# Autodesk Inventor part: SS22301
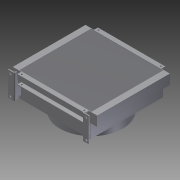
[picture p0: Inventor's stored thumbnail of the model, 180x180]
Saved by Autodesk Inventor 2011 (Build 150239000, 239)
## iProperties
Created: 2011-08
Part Number: SS22301
Document SubType Name: Modeling
Designer: khramov
Density: 1 g/cm^3
Author: khramov
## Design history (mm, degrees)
sketch "Эскиз1"
  geometry: L1 (0, 0)-(54, 0); L2 (538, 0)-(538, -464); L3 (538, -464)-(484, -464); L4 (0, -464)-(0, 0); L5 (0, -232)-(538, -232); L6 (54, 0)-(54, 25); L7 (54, 25)-(484, 25); L8 (484, 25)-(484, 0); L9 (484, 0)-(538, 0); L10 (54, -464)-(54, -489); L11 (54, -489)-(484, -489); L12 (484, -489)-(484, -464); L13 (54, -464)-(0, -464); L14 (70, 12.5)-(468, 12.5); L15 (468, 12.5)-(468, -476.5); L16 (468, -476.5)-(70, -476.5); L17 (70, -476.5)-(70, 12.5); L18 (269, 25)-(269, -489); C1 r 4.5 at (70, 12.5); C2 r 4.5 at (468, 12.5); C3 r 4.5 at (468, -476.5); C4 r 4.5 at (70, -476.5)
  constraints: 36 end point, 7 parallel, 7 perpendicular, 4 centre point, 4 coincident, 4 midpoint, 4 symmetric about line, 3 horizontal, 1 point on line
  dimensions: "d4" = 9 diameter of C4; "d5" = 9 diameter of C3; "d7" = 9 diameter of C1; "d38" = 538 distance between parallel lines of L2 L4; "d39" = 430 distance of L6.end L7.end; "d40" = 54 distance between parallel lines of L6 L4; "d41" = 25 distance of L1.end L6.end; "d42" = 514 distance between parallel lines of L11 L7; "d43" = 489 distance of L16.end L14.start; "d44" = 244.5 distance between parallel lines of L14 L5; "d45" = 398 distance of L14.start L14.end; "d46" = 199 distance between parallel lines of L18 L15; "d47" = 9 diameter of C2
extrude "Выдавливание1" new body sketch "Эскиз1" distance "d13" = 63; taper "d14" = 0 deg
sketch "Эскиз2"
  geometry: L1 (0, 0)-(54, 0) reference; L2 (54, -489)-(54, -464) reference; L3 (484, -464)-(484, -489) reference; L4 (538, -464)-(484, -464) reference; L5 (39, -3)-(499, -3); L6 (499, -3)-(499, -461); L7 (499, -461)-(39, -461); L8 (39, -461)-(39, -3)
  constraints: 8 end point, 2 parallel, 1 horizontal, 1 perpendicular
  dimensions: "d15" = 3 distance between parallel lines of L5 L1; "d16" = 3 distance between parallel lines of L7 L4; "d17" = 15 distance between parallel lines of L6 L3; "d18" = 15 distance between parallel lines of L2 L8
extrude "Выдавливание2" cut sketch "Эскиз2" distance "d19" = 2; taper "d20" = 0 deg
sketch "Эскиз3"
  geometry: L1 (-63, 25)-(-63, 0) reference; L2 (0, 25)-(0, 0) reference; L3 (0, 25)-(-63, 25) reference; L4 (-57, 25)-(-6, 25); L5 (-6, 25)-(-6, 0); L6 (-6, 0)-(-57, 0); L7 (-57, 0)-(-57, 25); L8 (0, -489)-(-63, -489) reference; L9 (-57, -489)-(-6, -489); L10 (-6, -489)-(-6, -464); L11 (-6, -464)-(-57, -464); L12 (-57, -464)-(-57, -489); L13 (0, 0)-(0, -464) reference; L14 (-63, 0)-(-63, -464) reference
  constraints: 16 end point, 4 parallel, 2 horizontal, 2 perpendicular, 2 point on line
  dimensions: "d21" = 6 distance between parallel lines of L7 L1; "d22" = 6 distance between parallel lines of L2 L5; "d23" = 25 distance between parallel lines of L6 L3; "d24" = 25 distance of L9.end L10.end; "d25" = 6 distance between parallel lines of L13 L10; "d26" = 6 distance between parallel lines of L14 L12
extrude "Выдавливание3" cut sketch "Эскиз3" stored distance "d27" = 2; taper "d28" = 0 deg
sketch "Эскиз4"
  geometry: L1 (0, 0)-(-54, 0) reference; L2 (-54, 0)-(-54, 25) reference; L3 (-484, 25)-(-484, 0) reference; L4 (-494, 0)-(-44, 0); L5 (-44, 0)-(-44, -464); L6 (-44, -464)-(-494, -464); L7 (-494, -464)-(-494, 0)
  constraints: 8 end point, 2 parallel, 1 horizontal, 1 perpendicular, 1 point on line
  dimensions: "d48" = 464 distance of L4.end L5.end; "d49" = 10 distance between parallel lines of L3 L7; "d50" = 10 distance between parallel lines of L2 L5
extrude "Выдавливание4" join sketch "Эскиз4" distance "d51" = 90; taper "d52" = 0 deg
sketch "Эскиз5"
  geometry: L1 (-494, 0)-(-44, -464); L2 (-44, 0)-(-494, -464); C1 r 200 at (-269, -232); 1 further point
  constraints: 4 end point, 1 centre point, 1 midpoint
  dimensions: "d53" = 400 diameter of C1
extrude "Выдавливание5" join sketch "Эскиз5" distance "d54" = 70; taper "d55" = 0 deg
sketch "Эскиз6"
  geometry: L1 (-269, -232)-(-269, -734.409); L2 (-484, -489)-(-54, -489) reference; L3 (-538, -464)-(-494, -464) reference; L4 (-491.5, -464)-(-491.5, -494); L5 (-497.5, -500)-(-526.5, -500); L6 (-526.5, -500)-(-526.5, -506); L7 (-526.5, -506)-(-491.5, -506); L8 (-485.5, -500)-(-485.5, -464); L9 (-511.5, -503.753)-(-511.5, -569.856); L10 (-11.5, -500)-(-11.5, -506); L11 (-11.5, -506)-(-46.5, -506); L12 (-40.5, -500)-(-11.5, -500); L13 (-46.5, -464)-(-46.5, -494); L14 (-52.5, -500)-(-52.5, -464); L15 (-26.5, -503.753)-(-26.5, -569.856); L16 (-491.5, -464)-(-485.5, -464); L17 (-538, -464)-(-484, -464) reference; L18 (-52.5, -464)-(-46.5, -464); L19 (-54, -464)-(0, -464) reference; C1 r 200 at (-269, -232) reference; A1 r 6 centre (-497.5, -494) between (-497.5, -500) and (-491.5, -494); A2 r 6 centre (-491.5, -500) between (-491.5, -506) and (-485.5, -500); A3 r 6 centre (-40.5, -494) between (-46.5, -494) and (-40.5, -500); A4 r 6 centre (-46.5, -500) between (-52.5, -500) and (-46.5, -506); 2 further points
  constraints: 31 end point, 13 symmetric about line, 8 point on circle, 4 centre point, 4 tangent, 3 parallel, 2 collinear, 2 perpendicular, 1 equal radius, 1 point on line, 2 other
  dimensions: "d56" = 6 distance of L5.end L6.end; "d57" = 6 distance between parallel lines of L4 L8; "d59" = 15 distance between parallel lines of L9 L6; "d60" = 20 distance between parallel lines of L4 L9; "d62" = 6 radius of A1; "d75" = 485 distance between parallel lines of L9 L15
extrude "Выдавливание6" join sketch "Эскиз6" distance "d63" = 166; taper "d65" = 0 deg; dims "d64" = 1, "d66" = 0
sketch "Эскиз7"
  geometry: L1 (-500, 15)-(-15, 15); L2 (-15, 15)-(-15, 141); L3 (-15, 141)-(-500, 141); L4 (-500, 141)-(-500, 15); L5 (-457.5, 236)-(-57.5, 236) reference; L6 (-257.5, 236)-(-257.5, 402.493); L7 (-472.5, 13)-(-42.5, 13) reference; C1 r 6.5 at (-500, 141); C2 r 6.5 at (-500, 15); C3 r 6.5 at (-15, 141); C4 r 6.5 at (-15, 15); 1 further point
  constraints: 10 end point, 4 centre point, 4 coincident, 2 parallel, 2 perpendicular, 1 horizontal, 1 midpoint
  dimensions: "d67" = 13 diameter of C1; "d68" = 13 diameter of C2; "d69" = 13 diameter of C3; "d70" = 13 diameter of C4; "d71" = 485 distance of L2.end L3.end; "d72" = 126 distance of L3.end L1.start; "d73" = 242.5 distance between parallel lines of L6 L4; "d76" = 2 distance between parallel lines of L1 L7
extrude "Выдавливание7" cut sketch "Эскиз7" distance "d77" = 10; taper "d78" = 0 deg
sketch "Эскиз8"
  geometry: L1 (-166, 15.676)-(-77.058, 26.142); L2 (-77.058, 26.142)-(-77.058, 42); L3 (-166, 42)-(-166, 15.676); L4 (-166, 42)-(-77.058, 42); L5 (-23.748, 26.142)-(-23.748, 42); L6 (-23.748, 42)-(-12.683, 42); L7 (-23.748, 26.142)-(-10, 16.534); L8 (-10, 0)-(0, 0); L9 (0, 0)-(0, 42); L10 (0, 42)-(-23.748, 42); L11 (-10, 16.534)-(-10, 0); 1 further point
  constraints: 22 end point, 3 perpendicular, 1 vertical
  dimensions: "d79" = 10 distance between parallel lines of L9 L11
extrude "Выдавливание8" cut sketch "Эскиз8" stored distance "d80" = 10; taper "d81" = 0 deg
sketch "Эскиз9"
  geometry: L1 (-166, 6)-(-166, 36) reference; L2 (-166, 8.721)-(-166, 36); L3 (-166, 36)-(-77.058, 36); L4 (-77.058, 20.142)-(-77.058, 36) reference; L5 (-77.058, 36)-(-77.058, 20.142); L6 (-77.058, 20.142)-(-166, 9.676); L7 (-77.058, 20.142)-(-166, 9.676) reference; L8 (0, 36)-(0, -6); L9 (0, 36)-(0, 0) reference; L10 (0, -6)-(-10, -6); L11 (-10, -6)-(-10, 0) reference; L12 (-10, -6)-(-10, 10.534); L13 (-10, 10.534)-(-23.748, 20.142); L14 (-10, 10.534)-(-23.748, 20.142) reference; L15 (-23.748, 20.142)-(-23.748, 36); L16 (-153, 36)-(0, 36) reference; L17 (-23.748, 36)-(0, 36); 1 further point
  constraints: 20 end point, 6 collinear, 2 parallel, 2 perpendicular, 2 point on line
extrude "Выдавливание9" cut sketch "Эскиз9" stored distance "d82" = 10; taper "d83" = 0 deg
sketch "Эскиз10"
  geometry: L1 (0, 464)-(63, 464) reference; L2 (0, 0)-(63, 0) reference; L3 (31.5, 464)-(31.5, 0); L4 (-80, -42)-(76, -42) reference; 2 further points
  constraints: 2 end point, 2 midpoint, 2 point on line
  dimensions: "d84" = 387 distance of point (31.5, 39.5) point (31.5, 426.5); "d85" = 81.5 distance from line of point (31.5, 39.5) L4
hole "Отверстие1" sketch "Эскиз10" at (31.5, 426.5), (31.5, 39.5) diameter "d86" = 30.291; stored, may be unused: countersink angle "d90" = 90 deg, drill point angle "d92" = 118 deg; dims "d87" = 45, "d88" = 34, "d89" = 2, "d91" = 50
node "Твердое тело1"
